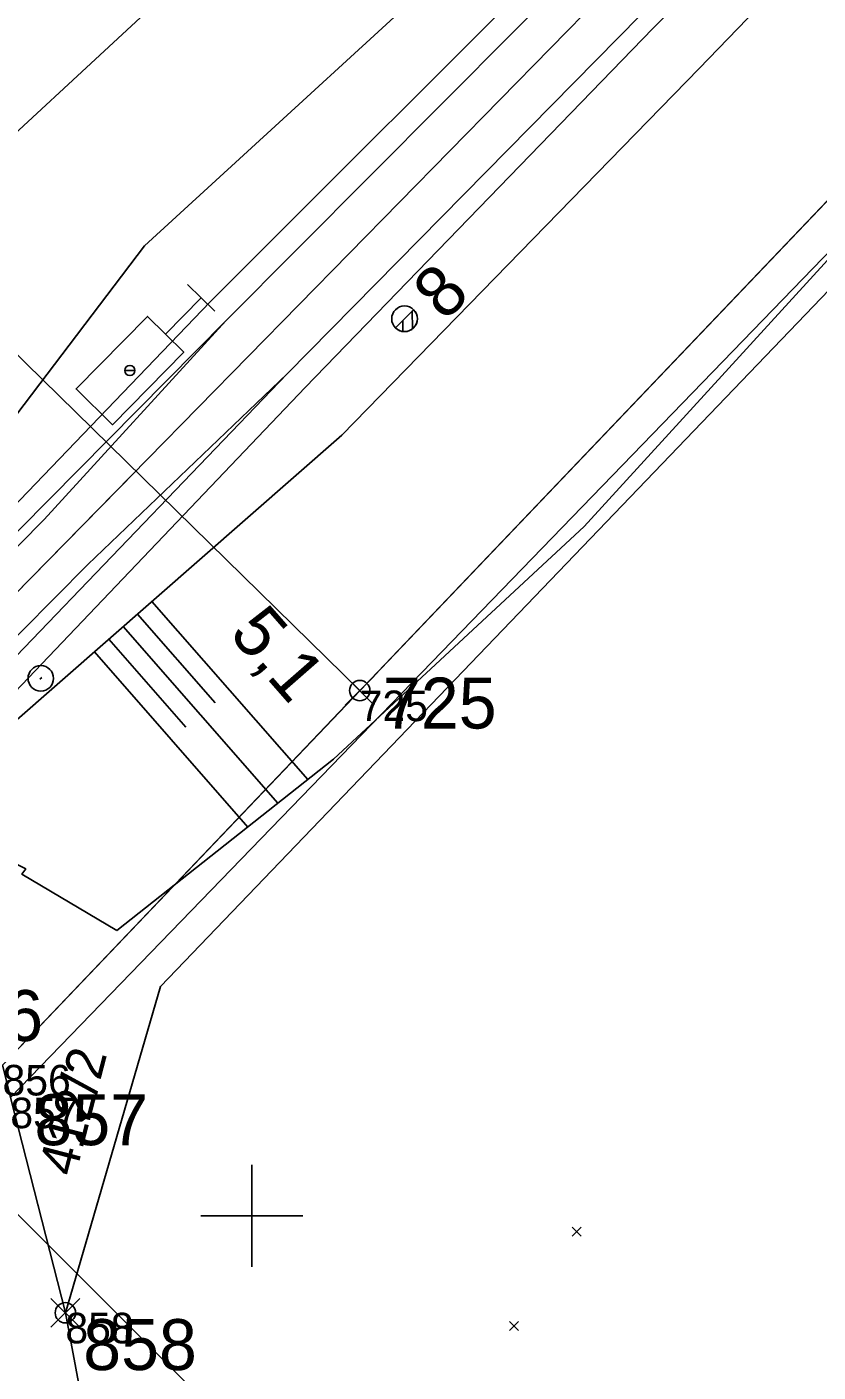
# Model space of a CAD drawing. Extents: x -800194 to -799078, y -1007177 to -1006597.
# Drawn here: x -799408.8 to -799377.8, y -1006906.1 to -1006853.3 of the extents above; entities that cross this region are included whole.
import ezdxf

# ---------------------------------------------------------------- set-up
doc = ezdxf.new("R2010")
doc.units = 0
for name, color, linetype in [('_návrh', 7, 'Continuous'), ('Dočasné zábory', 7, 'Continuous'), ('Obvod stavby', 7, 'Continuous'), ('Ramove udaje', 7, 'Continuous'), ('Vrstva 1', 7, 'Continuous'), ('Vrstva 11', 7, 'Continuous'), ('Vrstva 18', 7, 'Continuous'), ('Vrstva 4', 7, 'Continuous'), ('Vrstva 48', 7, 'Continuous'), ('Vrstva 49', 7, 'Continuous'), ('Vrstva 53', 7, 'Continuous'), ('Vrstva 55', 7, 'Continuous'), ('Vrstva 57', 7, 'Continuous'), ('Vrstva 60', 7, 'Continuous'), ('Vrstva 7', 7, 'Continuous')]:
    doc.layers.add(name, color=color, linetype=linetype)

msp = doc.modelspace()

# ---------------------------------------------------------------- linework, layer by layer
at = {"layer": '_návrh'}
msp.add_line((-799415.714, -1006882.127), (-799404.558, -1006870.75), dxfattribs=at)
at = {"layer": 'Dočasné zábory'}
for p, q in [((-799407.886, -1006904.376), (-799406.754, -1006903.244)), ((-799407.886, -1006903.244), (-799406.754, -1006904.376))]:
    msp.add_line(p, q, dxfattribs=at)
msp.add_lwpolyline([(-799409.787, -1006894.075), (-799409.48, -1006895.36), (-799407.32, -1006903.81), (-799399.52, -1006945.6), (-799393.3, -1006959.22), (-799387.62, -1006968.78), (-799386.5, -1006977.04), (-799373.965, -1006992.548), (-799373.809, -1006993.118), (-799373.66, -1006993.663), (-799374.581, -1006994.49), (-799377.093, -1006995.576), (-799395.454, -1007003.287), (-799408.652, -1007008.83)], dxfattribs=at)
msp.add_circle((-799407.32, -1006903.81), 0.4, dxfattribs=at)
at = {"layer": 'Obvod stavby'}
for p, q in [((-799396.329, -1006879.94), (-799395.197, -1006878.808)), ((-799396.329, -1006878.808), (-799395.197, -1006879.94))]:
    msp.add_line(p, q, dxfattribs=at)
msp.add_lwpolyline([(-799559.64, -1006968.48), (-799519.68, -1006952.01), (-799500.87, -1006940.41), (-799496.64, -1006937.8), (-799494.85, -1006936.7), (-799484.52, -1006930.32), (-799457.99, -1006908.8), (-799435, -1006885.17), (-799430.26, -1006880.27), (-799425.53, -1006875.38), (-799422.55, -1006864.36), (-799416.748, -1006858.798), (-799395.763, -1006879.374), (-799413.75, -1006898.23), (-799418.41, -1006902.53), (-799423.07, -1006906.83), (-799433.4, -1006916.39), (-799469.5, -1006946.86), (-799487.22, -1006958.47), (-799495.25, -1006963.74), (-799521.98, -1006977.8), (-799546.71, -1006987.83)], dxfattribs=at)
msp.add_circle((-799395.763, -1006879.374), 0.4, dxfattribs=at)
at = {"layer": 'Ramove udaje'}
for p, q in [((-799400, -1006898), (-799400, -1006902)), ((-799402, -1006900), (-799400, -1006900)), ((-799400, -1006900), (-799398, -1006900))]:
    msp.add_line(p, q, dxfattribs=at)
at = {"layer": 'Vrstva 1'}
msp.add_line((-799415.714, -1006882.127), (-799297.339, -1006761.401), dxfattribs=at)
at = {"layer": 'Vrstva 11'}
for p, q in [((-799393.651, -1006864.414), (-799394.357, -1006865.13)), ((-799394.068, -1006865.267), (-799394.071, -1006864.84)), ((-799393.693, -1006865.166), (-799393.699, -1006864.463))]:
    msp.add_line(p, q, dxfattribs=at)
msp.add_circle((-799394.004, -1006864.772), 0.503, dxfattribs=at)
msp.add_arc((-799394.004, -1006864.772), 0.503, 225.4308, 45.4308, dxfattribs=at)
at = {"layer": 'Vrstva 18'}
msp.add_line((-799380.318, -1006928.766), (-799419.546, -1006889.62), dxfattribs=at)
at = {"layer": 'Vrstva 4'}
for points in [[(-799415.349, -1006878.386), (-799401.641, -1006864.104), (-799387.486, -1006849.959), (-799372.535, -1006834.618), (-799359.471, -1006821.017), (-799348.425, -1006810.321), (-799332.246, -1006792.656), (-799316.193, -1006777.023)], [(-799414.896, -1006878.87), (-799401.02, -1006864.85), (-799386.827, -1006850.567), (-799372.152, -1006835.069), (-799358.827, -1006821.464), (-799347.624, -1006811), (-799330.977, -1006793.164), (-799315.559, -1006777.544)], [(-799412.388, -1006881.287), (-799398.609, -1006866.93), (-799384.751, -1006852.862), (-799369.474, -1006837.434), (-799356.035, -1006824.081), (-799345.419, -1006813.083), (-799328.801, -1006795.774), (-799312.796, -1006779.76)], [(-799411.693, -1006881.939), (-799397.907, -1006867.466), (-799384.258, -1006853.369), (-799368.884, -1006838.066), (-799355.624, -1006824.532), (-799352.562, -1006821.889), (-799351.649, -1006821.039), (-799351.009, -1006819.785)], [(-799510.394, -1006958.536), (-799498.027, -1006951.328), (-799477.988, -1006937.435), (-799460.33, -1006923.117), (-799451.862, -1006915.581), (-799443.604, -1006907.9), (-799435.444, -1006900.067), (-799428.64, -1006893.299), (-799422.817, -1006887.511), (-799415.998, -1006880.595), (-799408.158, -1006872.652), (-799401.02, -1006864.85)], [(-799509.248, -1006960.724), (-799497.456, -1006953.809), (-799476.495, -1006939.437), (-799458.707, -1006924.982), (-799450.277, -1006917.43), (-799441.932, -1006909.717), (-799433.783, -1006901.867), (-799426.9, -1006895.092), (-799421.037, -1006889.182), (-799414.218, -1006882.281), (-799406.443, -1006874.417), (-799398.609, -1006866.93)]]:
    msp.add_lwpolyline(points, dxfattribs=at)
at = {"layer": 'Vrstva 48'}
for p, q in [((-799403.924, -1006875.875), (-799397.802, -1006882.869)), ((-799404.488, -1006876.369), (-799401.44, -1006879.852)), ((-799405.053, -1006876.863), (-799398.98, -1006883.8)), ((-799405.617, -1006877.357), (-799402.593, -1006880.811)), ((-799406.181, -1006877.851), (-799400.158, -1006884.732))]:
    msp.add_line(p, q, dxfattribs=at)
at = {"layer": 'Vrstva 49'}
for p, q in [((-799387.424, -1006900.452), (-799387.07, -1006900.806)), ((-799387.424, -1006900.806), (-799387.07, -1006900.452)), ((-799389.887, -1006904.151), (-799389.533, -1006904.505)), ((-799389.887, -1006904.505), (-799389.533, -1006904.151))]:
    msp.add_line(p, q, dxfattribs=at)
for points in [[(-799327.095, -1006776.084), (-799339.676, -1006790.63), (-799358.716, -1006807.195), (-799375.729, -1006824.95), (-799393.254, -1006842.64), (-799410.738, -1006858.834), (-799418.516, -1006867.679), (-799420.397, -1006870.813)], [(-799416.02, -1006877.454), (-799404.211, -1006861.901), (-799389.752, -1006848.65), (-799373.943, -1006833.474), (-799360.851, -1006819.663), (-799350.223, -1006808.887), (-799332.885, -1006792.133), (-799317.349, -1006776.174)], [(-799405.305, -1006888.801), (-799396.789, -1006882.068), (-799386.952, -1006872.928), (-799372.538, -1006857.15), (-799356.348, -1006840.041), (-799339.512, -1006822.205), (-799317.886, -1006801.135), (-799302.503, -1006781.465)], [(-799411.244, -1006882.282), (-799396.463, -1006869.344), (-799382.442, -1006854.946), (-799367.277, -1006839.246), (-799355.518, -1006825.988), (-799351.844, -1006822.661), (-799350.97, -1006821.769), (-799343.258, -1006815.248), (-799325.688, -1006798.253), (-799311.274, -1006781.732)], [(-799413.881, -1006883.908), (-799408.874, -1006886.377), (-799409.032, -1006886.579), (-799405.305, -1006888.801)]]:
    msp.add_lwpolyline(points, dxfattribs=at)
at = {"layer": 'Vrstva 53'}
msp.add_lwpolyline([(-799312.398, -1006791.976), (-799331.37, -1006811.87), (-799413.75, -1006898.23), (-799418.41, -1006902.53), (-799423.07, -1006906.83), (-799433.4, -1006916.39), (-799469.5, -1006946.86), (-799487.22, -1006958.47), (-799495.25, -1006963.74), (-799521.98, -1006977.8), (-799546.71, -1006987.83)], dxfattribs=at)
at = {"layer": 'Vrstva 55'}
msp.add_line((-799413.75, -1006898.23), (-799331.37, -1006811.87), dxfattribs=at)
for points in [[(-799329.14, -1006812.3), (-799409.48, -1006895.36), (-799407.32, -1006903.81)], [(-799328.26, -1006812.47), (-799403.59, -1006891), (-799407.32, -1006903.81)], [(-799407.32, -1006903.81), (-799399.52, -1006945.6), (-799393.3, -1006959.22)]]:
    msp.add_lwpolyline(points, dxfattribs=at)
at = {"layer": 'Vrstva 60'}
for p, q in [((-799395.763, -1006879.374), (-799395.763, -1006879.374)), ((-799407.32, -1006903.81), (-799407.32, -1006903.81))]:
    msp.add_line(p, q, dxfattribs=at)
at = {"layer": 'Vrstva 7'}
for p, q in [((-799401.449, -1006864.476), (-799402.519, -1006863.424)), ((-799404.985, -1006866.805), (-799404.588, -1006866.802)), ((-799408.32, -1006878.93), (-799408.25, -1006878.858))]:
    msp.add_line(p, q, dxfattribs=at)
msp.add_lwpolyline([(-799401.984, -1006863.95), (-799403.386, -1006865.377), (-799404.099, -1006864.676), (-799406.902, -1006867.529), (-799405.475, -1006868.931), (-799402.672, -1006866.078), (-799403.386, -1006865.377)], dxfattribs=at)
for centre, radius in [((-799404.787, -1006866.803), 0.2), ((-799408.285, -1006878.894), 0.5)]:
    msp.add_circle(centre, radius, dxfattribs=at)

# ---------------------------------------------------------------- texts
at = {"layer": 'Dočasné zábory'}
for s, p in [('856', (-799412.658, -1006893.137)), ('857', (-799408.534, -1006897.227)), ('858', (-799406.62, -1006906.059))]:
    msp.add_text(s, height=2, rotation=360, dxfattribs=at).set_placement(p)
at = {"layer": 'Obvod stavby'}
msp.add_text('725', height=2, rotation=360, dxfattribs=at).set_placement((-799394.852, -1006880.864))
at = {"layer": 'Vrstva 11'}
msp.add_text('8', height=2, rotation=45.4308, dxfattribs=at).set_placement((-799392.413, -1006864.91))
at = {"layer": 'Vrstva 48'}
msp.add_text('5,1', height=2, rotation=311.1961, dxfattribs=at).set_placement((-799400.935, -1006877.17))
at = {"layer": 'Vrstva 57'}
msp.add_text('412/2', height=1.5, rotation=75.4361, dxfattribs=at).set_placement((-799406.937, -1006898.504))
at = {"layer": 'Vrstva 60'}
for s, p in [('725', (-799395.763, -1006880.574)), ('856', (-799409.787, -1006895.275)), ('857', (-799409.48, -1006896.56)), ('858', (-799407.32, -1006905.01))]:
    msp.add_text(s, height=1.2, dxfattribs=at).set_placement(p)

doc.saveas('drawing.dxf')
